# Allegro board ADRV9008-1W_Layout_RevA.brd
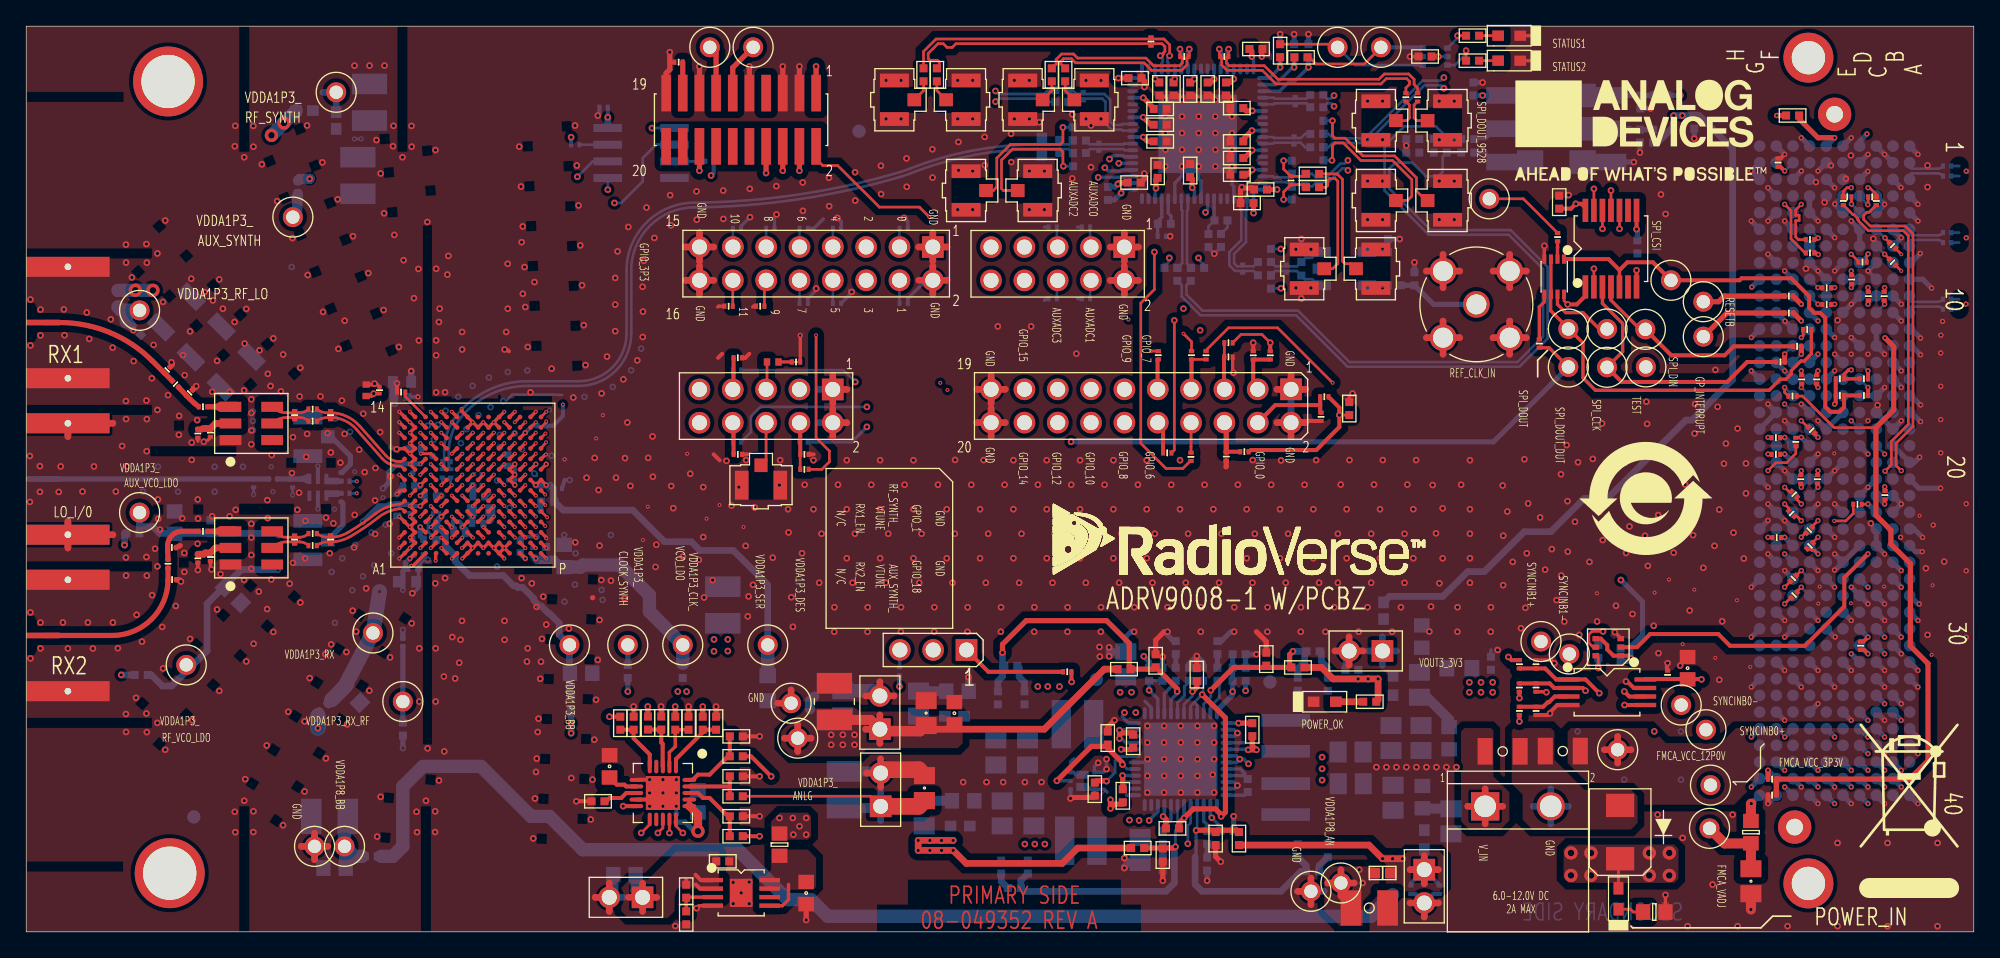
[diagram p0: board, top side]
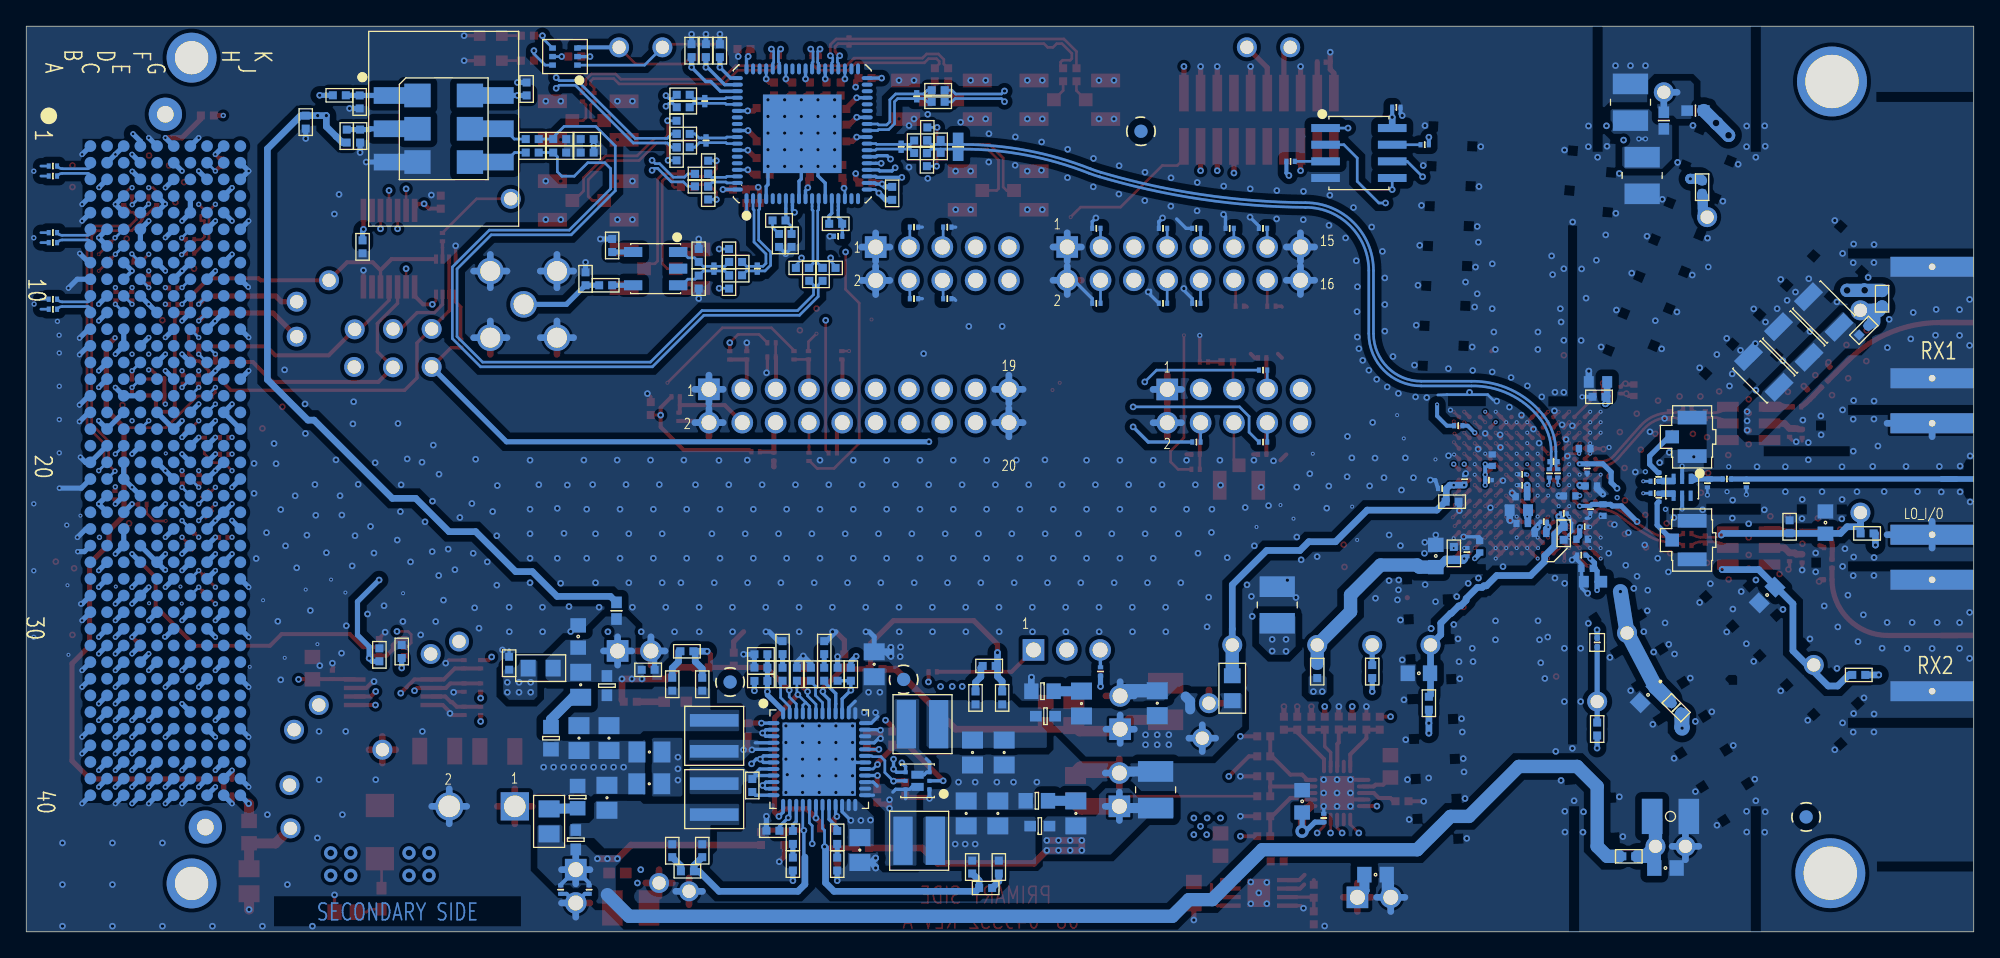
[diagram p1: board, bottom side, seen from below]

Outline 148.44 x 69.09 mm; copper layers: TOP, L2_GND, L3_PWR, L4_GND, L5_SIG, L6_GND, L7_SIG, L8_SIG, L9_GND, L10_SIG, L11_GND, L12_PWR, L13_GND, BOTTOM. Coordinates in mm from the lower left corner of the outline.
Outline path: 0,69.09 0,0 148.44,0 148.44,69.09 0,69.09

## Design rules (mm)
constraint set DEFAULT: min track width 0.203
net group DIFFPAIR0: nets SERDOUT0+ SERDOUT0-
net group DIFFPAIR1: nets SERDOUT1+ SERDOUT1-
net group DIFFPAIR2: nets SERDOUT3+ SERDOUT3-
net group DIFFPAIR13: nets SERDOUT2+ SERDOUT2-
net group DIFFPAIR26: nets GPIO_16 GPIO_17
net group DIFFPAIR27: nets GPIO_13 GPIO_14
net group DIFFPAIR28: nets GPIO_11 GPIO_12
net group DIFFPAIR29: nets GPIO_9 GPIO_10
net group DIFFPAIR30: nets GPIO_8 GPIO_15
net group DIFFPAIR37: nets SYNCINB0+ SYNCINB0-
net group DIFFPAIR38: nets SYNCINB1+ SYNCINB1-
net group DIFFPAIR56: nets SYSREF_IN+ SYSREF_IN-
net group DIFFPAIR59: nets CLK+ CLK-
net group DIFFPAIR63: nets FPGA_SYSREF+ FPGA_SYSREF-
net group DIFFPAIR72: nets VCXO_IN+ VCXO_IN-
net group DIFFPAIR74: nets FPGA_REF_CLK+ FPGA_REF_CLK-
net group DIFFPAIR75: nets DIR_CLK+ DIR_CLK-
net group DIFFPAIR76: nets UNNAMED_2_CAP_I91_N2 UNNAMED_2_CAP_I92_N2
net group DIFFPAIR77: nets UNNAMED_2_ADRV90081_I127_SERDOU UNNAMED_2_CAP_I94_N2
net group DIFFPAIR78: nets UNNAMED_2_CAP_I95_N2 UNNAMED_2_CAP_I98_N2
net group DIFFPAIR82: nets UNNAMED_2_CAP_I96_N2 UNNAMED_2_CAP_I97_N2
net group DIFFPAIR84: nets UNNAMED_7_CN400PAK_I55_N15 UNNAMED_7_CN400PAK_I55_N16
net group DIFFPAIR85: nets UNNAMED_7_CN400PAK_I55_N21 UNNAMED_7_CN400PAK_I55_N22
net group DIFFPAIR86: nets UNNAMED_7_CN400PAK_I52_N22 UNNAMED_7_CN400PAK_I52_N23
net group DIFFPAIR87: nets UNNAMED_7_CN400PAK_I55_N24 UNNAMED_7_CN400PAK_I55_N25
net group DIFFPAIR88: nets UNNAMED_4_CAP_I184_N1 UNNAMED_4_RES_I165_N2
net group DIFFPAIR89: nets OUT3 OUT3_N
net group DIFFPAIR91: nets OUT1 OUT1_N
net group DIFFPAIR92: nets UNNAMED_4_CAP_I166_N1 UNNAMED_4_CAP_I177_N1
net group DIFFPAIR93: nets OUT13 OUT13_N
net group DIFFPAIR94: nets OUT12 OUT12_N
net group DIFFPAIR96: nets UNNAMED_7_CAP_I157_N2 UNNAMED_7_CAP_I158_N2
net group DIFFPAIR98: nets SYSREF_CLK_IN+ SYSREF_CLK_IN-
net group DIFFPAIR99: nets FPGA_SYSREF_OUT+ FPGA_SYSREF_OUT-
net group DIFFPAIR100: nets UNNAMED_4_CNBNC3P_I324_CNTR UNNAMED_4_CNBNC3P_I325_CNTR
net group DIFFPAIR101: nets UNNAMED_4_CAP_I329_N1 UNNAMED_4_CAP_I330_N1
net group DIFFPAIR102: nets REF_CLK_IN+ REF_CLK_IN-
net group DIFFPAIR105: nets RX1_IN+ RX1_IN-
net group DIFFPAIR106: nets RX1_BAL+ RX1_BAL-
net group DIFFPAIR107: nets RF_EXT_LO+ RF_EXT_LO-
net group DIFFPAIR108: nets UNNAMED_10_CAP_I10_N1 UNNAMED_10_CAP_I11_N1
net group DIFFPAIR109: nets RX2_IN+ RX2_IN-
net group DIFFPAIR110: nets RX2_BAL+ RX2_BAL-
net group DIFFPAIR113: nets UNNAMED_4_CNBNC3P_I318_CNTR UNNAMED_4_CNBNC3P_I321_CNTR
net group DIFFPAIR114: nets UNNAMED_4_CAP_I292_N2 UNNAMED_4_CAP_I294_N2
net group DIFFPAIR115: nets OUT5 OUT5_N
net group DIFFPAIR116: nets UNNAMED_4_CAP_I303_N2 UNNAMED_4_CAP_I304_N2
net group DIFFPAIR117: nets OUT7 OUT7_N
net group DIFFPAIR118: nets UNNAMED_4_CNBNC3P_I306_CNTR UNNAMED_4_CNBNC3P_I308_CNTR
net group DIFFPAIR119: nets OUT8 OUT8_N
net group DIFFPAIR120: nets UNNAMED_4_CNBNC3P_I148_CNTR UNNAMED_4_CNBNC3P_I248_CNTR
nets with their own width: min track width 0.254; nets AGND

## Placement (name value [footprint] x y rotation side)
C6  0.1uF  [C0402]  111.64 20.49 270 bottom
C101  1uF  [C0402#2]  37.66 29.38 90 bottom
C102  1uF  [C0402#2]  30.8 33.25 0 bottom
C103  0.1uF  [C0201]  32.34 34.97 270 bottom
C104  0.1uF  [C0201]  31.71 34.97 270 bottom
C105  0.1uF  [C0201]  146.41 58.42 0 bottom
C106  0.1uF  [C0201]  146.41 57.66 0 bottom
C107  0.1uF  [C0201]  146.41 53.34 0 bottom
C108  0.1uF  [C0201]  146.41 52.58 0 bottom
C109  0.1uF  [C0201]  142.25 52.35 315 top
C110  0.1uF  [C0201]  142.25 51.08 315 top
C111  0.1uF  [C0201]  146.41 48.26 0 bottom
C112  0.1uF  [C0201]  146.41 47.5 0 bottom
C121  0.1uF  [C0201]  66.87 53.67 0 bottom
C122  0.1uF  [C0201]  66.87 47.95 0 bottom
C123  0.1uF  [C0201]  61.79 53.67 0 bottom
C124  0.1uF  [C0201]  61.79 47.95 0 bottom
C125  0.1uF  [C0201]  59.25 53.67 0 bottom
C126  0.1uF  [C0201]  59.25 47.95 0 bottom
C127  0.1uF  [C0201]  56.71 53.67 0 bottom
C128  0.1uF  [C0201]  55.95 47.73 180 top
C129  0.1uF  [C0201]  54.17 53.67 0 bottom
C130  0.1uF  [C0201]  53.53 47.73 180 top
C131  0.1uF  [C0201]  80.77 53.76 180 bottom
C132  0.1uF  [C0201]  80.77 48.3 180 bottom
C133  0.1uF  [C0201]  78.23 53.76 180 bottom
C134  0.1uF  [C0201]  78.23 48.3 180 bottom
C135  0.1uF  [C0201]  44.01 62.9 180 bottom
C136  1uF  [C0402#2]  56.9 43.47 0 top
C137  1uF  [C0402#2]  29.66 36.87 180 bottom
C201  TBD0201  [C0201]  10.74 42.87 45 top
C203  TBD0201  [C0201]  12.45 41.12 45 top
C204  TBD0201  [C0201]  20.46 39.42 90 top
C207  TBD0201  [C0201]  23.2 39.42 90 top
C208  TBD0201  [C0201]  11.12 26.87 0 top
C210  TBD0201  [C0201]  11.09 29.31 0 top
C211  TBD0201  [C0201]  20.46 29.92 90 top
C214  TBD0201  [C0201]  23.2 29.92 90 top
C240  10pF  [C0201]  13.08 38.01 90 top
C241  27PF  [C0201]  14.04 38.08 90 top
C242  82PF  [C0201]  14.04 28.59 90 top
C243  27PF  [C0201]  13.08 28.49 270 top
C248  18PF  [C0201]  13.47 40.05 0 top
C249  18PF  [C0201]  13.47 30.56 0 top
C301  TBD0201  [C0201]  17.33 34.23 270 bottom
C303  TBD0201  [C0201]  20.3 34.23 270 bottom
C304  100pF  [C0201]  24.32 34.37 0 bottom
C305  100pF  [C0201]  24.32 33.45 0 bottom
C401  0.1uF  [C0402]  104.28 49.32 180 bottom
C402  0.1uF  [C0402]  94.87 51.6 90 bottom
C403  0.1uF  [C0402]  94.37 51.1 180 bottom
C404  0.1uF  [C0402]  94.87 49.57 270 bottom
C405  0.1uF  [C0402]  94.37 50.09 180 bottom
C406  0.33uF  [C0402]  123.02 63.31 270 bottom
C407  0.1uF  [C0402]  110.3 64.3 270 bottom
C408  0.1uF  [C0402]  105.68 59.45 180 bottom
C409  0.1uF  [C0402]  88.76 50.16 90 bottom
C410  100pF  [C0201]  105.16 63.67 270 top
C411  100pF  [C0201]  106.05 63.67 270 top
C412  0.01uF  [C0402]  78.17 65.38 270 top
C413  0.01uF  [C0402]  79.19 65.38 270 top
C414  180pF  [C0402]  90.11 52.74 90 bottom
C415  1uF  [C0402]  91.06 52.74 90 bottom
C416  1000pF  [C0402]  86.74 54.01 0 bottom
C417  0.47uF  [C0201]  86.55 53.06 0 bottom
C418  0.1uF  [C0402]  86.43 60.3 0 top
C419  0.1uF  [C0402]  96.46 58.33 270 bottom
C420  0.1uF  [C0402]  96.46 56.36 90 bottom
C421  0.1uF  [C0402]  121.52 21.13 270 bottom
C422  0.1uF  [C0402]  119.82 21.38 270 bottom
C423  0.1uF  [C0402]  122.81 52.26 90 bottom
C424  0.1uF  [C0402]  116.84 55.67 270 top
C425  0.1uF  [C0402]  100.84 39.92 90 top
C426  1uF  [C0402]  86.24 58.02 90 top
C427  0.1uF  [C0402]  88.71 58.08 270 top
C428  0.1uF  [C0402]  93.04 55.6 0 top
C429  0.1uF  [C0402]  94.08 56.63 0 top
C430  0.1uF  [C0402]  92.27 57.76 0 top
C431  0.1uF  [C0402]  92.27 59.03 0 top
C432  0.1uF  [C0402]  92.27 60.3 0 top
C433  0.1uF  [C0402]  92.27 62.84 0 top
C434  0.1uF  [C0402]  93.73 67.35 180 top
C435  0.1uF  [C0402]  91.44 64.3 90 top
C436  0.1uF  [C0402]  90.05 64.3 90 top
C437  0.1uF  [C0402]  88.71 64.3 90 top
C438  0.1uF  [C0402]  87.44 64.3 90 top
C439  0.1uF  [C0402]  86.36 64.3 90 top
C440  0.1uF  [C0402]  106.62 66.78 0 top
C441  0.1uF  [C0402]  84.45 57.16 180 top
C442  0.1uF  [C0402]  86.43 61.57 180 top
C443  0.1uF  [C0402]  86.43 62.78 180 top
C444  0.1uF  [C0402]  84.51 65.13 180 top
C445  TBD0402  [C0402]  78.74 59.92 270 bottom
C601  10uF  [C0603]  70.74 16.68 90 top
C602  220UF  [C1210-2]  61.6 17.57 90 top
C603  10uF  [C0603]  42.29 19.72 0 bottom
C604  0.1uF  [C0201]  31.24 31.92 180 bottom
C605  1uF  [C0402]  31.25 30.4 270 bottom
C606  220UF  [C1210-2]  25.28 57.7 270 bottom
C607  220UF  [C1210-2]  26.16 63.29 90 bottom
C608  0.1uF  [C0201]  34.42 34.08 0 bottom
C609  1uF  [C0402#2]  34.48 33.19 0 bottom
C610  10uF  [C0603]  41 28.67 90 bottom
C611  0.1uF  [C0201]  38.63 28.96 90 bottom
C612  1uF  [C0402]  39.63 28.87 90 bottom
C613  10uF  [C0603#2]  29.02 26.71 0 bottom
C614  1uF  [C0402#2]  29.47 27.73 0 bottom
C615  0.1uF  [C0201]  29.91 28.74 0 bottom
C616  10uF  [C0603#2]  34.67 32.17 0 bottom
C617  1uF  [C0402#2]  34.42 31.15 0 bottom
C618  10uF  [C0603]  24.83 18.08 315 bottom
C619  0.1uF  [C0201]  29.66 30.9 180 bottom
C620  1uF  [C0402#2]  29.85 29.95 180 bottom
C621  10uF  [C0603]  11.31 31.22 90 bottom
C622  0.1uF  [C0201]  29.47 35.35 270 bottom
C623  1uF  [C0402]  14.04 30.9 90 bottom
C624  220UF  [C1210-2#2]  13.72 45 45 bottom
C625  220UF  [C1210-2#2]  11.43 47.28 45 bottom
C626  220UF  [C1210-2#2]  16 42.71 45 bottom
C627  1uF  [C0402#2]  29.15 34.01 180 bottom
C628  10uF  [C0603]  15.75 25.69 315 bottom
C629  0.1uF  [C0201]  29.21 32.23 270 bottom
C630  1uF  [C0402#2]  28.26 32.17 270 bottom
C631  10uF  [C0603#2]  28.64 41.95 0 bottom
C632  0.1uF  [C0201]  34.42 34.9 0 bottom
C633  1uF  [C0402]  28.56 40.81 0 bottom
C634  0.1uF  [C0201]  40.52 33.82 0 bottom
C635  1uF  [C0402]  39.76 32.81 180 bottom
C636  0.1uF  [C0201]  38.8 34.52 90 bottom
C640  220UF  [C1210-2]  62.36 10.83 90 bottom
C641  220UF  [C1210-2]  53.09 24.93 90 bottom
C642  0.1uF  [C0201]  36.96 34.46 180 bottom
C643  1uF  [C0402#2]  36.71 35.98 90 bottom
C701  0.1uF  [C0201]  49.54 8.68 270 bottom
C702  10uF  [C0603]  51.19 9.95 90 bottom
C703  10uF  [C0603]  126.63 20.11 90 top
C704  0.1uF  [C0201]  125.1 19.6 90 top
C705  10uF  [C0603]  44.46 12.62 90 top
C706  1uF  [C0402]  43.58 9.96 180 top
C801  0.01uF  [C0201]  140.7 56.06 180 top
C802  0.01uF  [C0201]  138.8 56.06 0 top
C803  0.01uF  [C0201]  141.01 55.76 270 top
C804  0.01uF  [C0201]  138.5 55.76 270 top
C901  10uF  [C0805H60]  83.81 20.41 90 bottom
C902  1uF  [C0402]  89.7 19.65 270 bottom
C903  1uF  [C0402]  89.22 19.62 270 top
C904  0.0027uF  [C0402]  87.62 21.68 270 bottom
C905  10uF  [C0805H60]  84.9 6.24 270 bottom
C906  0.0027uF  [C0402]  86.63 5.17 90 bottom
C907  10uF  [C0805H60]  100.94 13.72 0 bottom
C908  0.0033uF  [C0402]  90.79 21.68 270 bottom
C909  10uF  [C0805H60]  100.95 11.29 0 bottom
C910  0.0033uF  [C0402]  90 5.17 90 bottom
C911  TBD0402  [C0402]  86.6 19.65 270 bottom
C912  TBD0402  [C0402]  92.44 21.17 180 bottom
C913  0.1uF  [C0402]  84.37 14.54 90 top
C914  0.01uF  [C0402]  76.09 17.84 270 bottom
C915  0.1uF  [C0402]  83.58 10.38 90 top
C916  0.01uF  [C0402]  74.31 4.94 90 bottom
C917  0.1uF  [C0402]  93.45 15.42 270 top
C918  0.01uF  [C0402]  99.2 18.88 270 bottom
C919  0.1uF  [C0402]  93.1 11.16 90 bottom
C920  0.01uF  [C0402]  99.2 6.18 90 bottom
C921  47uF  [C0805H60]  76.31 13.68 270 bottom
C922  47uF  [C0805H60]  73.9 13.68 270 bottom
C924  47uF  [C0805H60]  68.01 17.41 90 bottom
C925  47uF  [C0805H60]  76.8 9.03 90 bottom
C926  47uF  [C0805H60]  74.38 9.03 90 bottom
C927  47uF  [C0805H60]  68.44 9.03 90 bottom
C928  47uF  [C0805H60]  104.02 14.78 270 bottom
C929  47uF  [C0805H60]  106.18 18.84 270 bottom
C930  47uF  [C0805H60]  104.18 10.22 90 bottom
C931  22uF  [C0805H53]  108.59 8.42 90 bottom
C932  47uF  [C0805H60]  131.45 3.86 270 top
C933  4.7uF  [C0603]  59.45 2.96 90 top
C934  4.7uF  [C0603]  45.6 4.36 0 bottom
C935  0.01uF  [C0402]  53.09 5.37 180 top
C936  10uF  [C0603]  106.37 22.53 90 bottom
C937  0.01uF  [C0402]  101.04 19.99 0 bottom
C938  0.1uF  [C0402]  127.14 61.77 90 bottom
C939  47uF  [C0805H60]  106.31 14.78 270 bottom
C940  0.1uF  [C0201]  105.54 3.21 90 bottom
C941  0.01uF  [C0201]  107.7 3.21 90 bottom
C942  100uF  [C1210]  23.12 8.8 180 bottom
C943  10uF  [C0603]  23.5 4.87 180 bottom
C944  0.1uF  [C0201]  32.77 31.28 0 bottom
C945  1uF  [C0402#2]  33.02 30.39 0 bottom
C946  100uF  [C1210]  102.36 1.82 0 top
C947  0.1uF  [C0201]  26.93 41.31 90 top
C948  1uF  [C0402#2]  25.91 41.31 90 top
C949  47uF  [C0805H60]  62.23 17.44 90 bottom
C950  47uF  [C0805H60]  68.59 16.68 90 top
C951  47uF  [C0805H60]  68.46 10.97 90 top
CR901  S2A-LT  [DO214AA3]  121.48 7.6 90 top
DS401  LNJ326W83RA  [LED0603_A]  113.03 66.46 180 top
DS402  LNJ326W83RA  [LED0603_A]  113.03 68.37 180 top
DS901  LNJ926W8CRA  [LED0603]  121.36 2.52 90 top
DS902  LNJ326W83RA  [LED0603_A]  98.97 17.55 0 top
E602  1.8K OHM AT 100MEGHZ  [L0402]  21.21 62.65 0 bottom
E611  42OHM AT 100MEGHZ  [L0805]  56.52 18.58 90 bottom
E613  1.8KOHM AT 100MEGHZ  [L0402]  23.62 61.89 270 bottom
E901  120OHM  [L0603]  70.75 16.45 180 bottom
E902  470OHM  [L0603]  71.18 8.06 180 bottom
E903  470OHM  [L0603]  104.18 18.78 90 bottom
E904  470OHM  [L0603]  106.56 7.02 270 bottom
E905  42OHM AT 100MEGHZ  [L0805]  109.23 20.11 0 bottom
E906  30OHM  [L0402]  103.45 24.49 90 bottom
E907  30OHM  [L0402]  103.38 4.48 180 top
F901  2A  [F1206]  117.11 13.78 180 top
F902  2A  [F1206]  112.53 13.76 0 top
J101  U.FL-R-SMT-1(01)  [CNHIROSE-U_FL-R-SMT-1]  56 34.07 180 top
J201  132255-11  [CNAMPHENOL132255-11]  0.76 46.48 180 top
J202  132255-11  [CNAMPHENOL132255-11]  0.76 22.61 180 top
J301  132255-11  [CNAMPHENOL132255-11]  0.76 34.54 180 bottom
J305  U.FL-R-SMT-1(01)  [CNHIROSE-U_FL-R-SMT-1]  21.47 37.76 270 bottom
J306  U.FL-R-SMT-1(01)  [CNHIROSE-U_FL-R-SMT-1]  21.47 29.88 270 bottom
J401  142-0701-201  [CNJOHNSON142-0701-201]  110.53 47.87 0 top
J402  U.FL-R-SMT-1(01)  [CNHIROSE-U_FL-R-SMT-1]  102.87 55.79 90 top
J403  U.FL-R-SMT-1(01)  [CNHIROSE-U_FL-R-SMT-1]  108.33 55.79 270 top
J404  U.FL-R-SMT-1(01)  [CNHIROSE-U_FL-R-SMT-1]  102.87 61.89 90 top
J405  U.FL-R-SMT-1(01)  [CNHIROSE-U_FL-R-SMT-1]  108.33 61.89 270 top
J406  U.FL-R-SMT-1(01)  [CNHIROSE-U_FL-R-SMT-1]  75.95 63.48 90 top
J407  U.FL-R-SMT-1(01)  [CNHIROSE-U_FL-R-SMT-1]  81.41 63.48 270 top
J408  U.FL-R-SMT-1(01)  [CNHIROSE-U_FL-R-SMT-1]  71.63 63.48 270 top
J409  U.FL-R-SMT-1(01)  [CNHIROSE-U_FL-R-SMT-1]  66.17 63.48 90 top
J410  U.FL-R-SMT-1(01)  [CNHIROSE-U_FL-R-SMT-1]  71.63 56.55 90 top
J411  U.FL-R-SMT-1(01)  [CNHIROSE-U_FL-R-SMT-1]  77.09 56.55 270 top
J412  U.FL-R-SMT-1(01)  [CNHIROSE-U_FL-R-SMT-1]  102.87 50.59 270 top
J413  U.FL-R-SMT-1(01)  [CNHIROSE-U_FL-R-SMT-1]  97.41 50.59 90 top
L401  TBD0402  [L0402]  77.41 59.89 90 bottom
L612  TBD0201  [L0201]  28.7 22.07 90 bottom
L900  2.2uH  [LSMSQ157H83]  80.12 15.84 180 bottom
L901  2.2uH  [LSMSQ157H83]  80.38 6.95 180 bottom
L902  6.8uH  [LSMSQ157H122]  96 14.95 90 bottom
L903  6.8uH  [LSMSQ157H122]  96 10.12 270 bottom
NOREF  -  []  65.26 90.52 0 top
NOREF#2  -  [unnamed#2]  10.81 64.87 0 top
NOREF#3  -  []  -140.27 -283.34 0 top
NOREF#4  -  []  152.78 19.47 0 top
NOREF#5  -  []  123.45 33.06 0 top
NOREF#6  -  []  250.38 218.8 0 top
NOREF#7  -  []  0 69.09 0 top
NOREF#8  -  [unnamed#2]  135.84 66.69 0 top
NOREF#9  -  []  123.07 61.13 0 top
NOREF#10  -  []  100.91 114.35 0 top
NOREF#11  -  []  3.55 -12.7 90 top
NOREF#12  -  [unnamed#2]  10.93 4.47 0 top
NOREF#13  -  []  154.73 137.11 0 top
NOREF#14  -  []  148.44 0 90 top
NOREF#15  -  []  280.93 -40.72 0 top
NOREF#16  -  []  -140.27 -283.34 0 top
NOREF#17  -  [unnamed#2]  135.84 3.69 0 top
NOREF#18  -  []  -140.27 -283.34 0 top
NOREF#19  -  []  -96.05 -19.57 0 top
NOREF#20  -  [unnamed#2]  94.79 19.06 0 bottom
NOREF#21  -  [unnamed#2]  12.78 8.76 0 bottom
NOREF#22  -  [unnamed#2]  81.56 19.25 0 bottom
NOREF#23  -  [unnamed#2]  63.47 61.07 90 bottom
P101  TSW-110-08-G-D  [CNBERG2X10H330LD36]  96.4 41.39 180 top
P102  TSW-108-08-G-D  [CNSAMTECTSW-108-08-G-D-ST]  69.1 52.24 180 top
P103  TSW-105-08-G-D  [CNSAMTEC2X5H338LD36]  83.7 52.24 180 top
P104  TSW-105-08-G-D  [CNSAMTEC2X5H338LD36]  61.47 41.38 180 top
P701  FTSH-110-01-L-DV-K  [CNHDR2X10H251]  54.49 61.95 180 top
P801  ASP-134488-01  [CNSAMTECASP-134488-01]  143.55 59.94 270 bottom
P901  Z5.530.3225.0  [CNWIELAND3225]  111.2 9.57 0 top
P902  TSW-103-08-G-S  [CNBERG1X3H205LD36]  71.67 21.5 180 top
P903  TSW-102-08-G-S  [CNSAMTEC1X2H330LD36]  65.06 16.73 90 top
P904  TSW-102-08-G-S  [CNSAMTEC1X2H330LD36]  65.12 10.84 90 top
P905  TSW-102-08-G-S  [CNSAMTEC1X2H330LD36]  102.1 21.42 180 top
P906  TSW-102-08-G-S  [CNSAMTEC1X2H330LD36]  106.56 3.47 270 top
P907  TSW-102-08-G-S  [CNSAMTEC1X2H330LD36]  45.71 2.63 180 top
Q901  SIA906EDJ-T1-GE3  [POWERPAKSC70-6]  80.51 11.52 90 bottom
R101  14.3K  [R0201]  28.57 41.18 180 top
R102  10K  [R0201]  91.63 44.93 180 top
R103  10K  [R0201]  91.63 43.85 0 top
R104  10K  [R0201]  92.85 36.62 180 top
R105  10K  [R0201]  91.46 36.25 270 top
R106  10K  [R0201]  94.81 43.98 270 top
R107  10K  [R0201]  93.52 43.98 90 top
R108  10K  [R0201]  98.94 40.81 180 top
R109  10K  [R0201]  98.69 39.29 270 top
R110  10K  [R0201]  39.29 38.61 0 bottom
R111  10K  [R0201]  133.07 11.65 0 top
R112  1K  [R0201]  133.07 10.43 180 top
R113  10K  [R0201]  59.31 36.43 0 top
R116  10K  [R0201]  54.23 36.43 0 top
R117  10K  [R0201]  54.23 43.79 0 top
R118  10K  [R0201]  58.68 43.47 0 top
R119  10K  [R0201]  41.85 60.05 0 bottom
R120  10K  [R0201]  52.07 58.78 180 bottom
R121  100  [R0201]  32.03 35.86 180 bottom
R202  0  [R0201]  11.38 41.78 315 top
R205  0  [R0201]  21.83 38.96 0 top
R206  0  [R0201]  21.83 39.87 0 top
R209  0  [R0201]  10.8 28.08 90 top
R212  0  [R0201]  21.83 29.47 0 top
R213  0  [R0201]  21.83 30.38 0 top
R302  0  [R0201]  18.82 34.54 0 bottom
R304  0  [R0201]  24.01 34.71 270 bottom
R305  0  [R0201]  24.01 33.12 90 bottom
R401  49.9  [R0402]  105.81 49.82 270 bottom
R402  0  [R0402]  103.78 52.36 270 bottom
R403  24.9  [R0402]  97.18 51.6 90 bottom
R404  24.9  [R0402]  97.18 49.57 90 bottom
R405  100  [R0201]  96.02 50.59 270 bottom
R406  100  [R0201]  92.72 50.59 270 bottom
R407  0  [R0402]  124.57 63.82 180 bottom
R408  0  [R0402]  124.01 60.71 90 bottom
R409  0  [R0402]  122.99 60.71 90 bottom
R410  0  [R0402]  109.87 59.45 180 bottom
R411  0  [R0402]  87.74 50.16 90 bottom
R412  49.9  [R0402]  107.78 59.45 0 bottom
R413  0  [R0402]  107.78 60.48 180 bottom
R414  0  [R0402]  105.68 60.48 180 bottom
R415  0  [R0402]  87.25 50.65 180 bottom
R416  0  [R0402]  89.28 50.65 0 bottom
R417  0  [R0402]  109.87 60.48 180 bottom
R418  100  [R0201]  96.63 60.37 270 bottom
R419  0  [R0402]  98.36 59.86 0 bottom
R420  0  [R0402]  98.36 60.87 0 bottom
R421  0  [R0402]  98.87 59.35 90 bottom
R422  0  [R0402]  98.87 61.38 270 bottom
R423  100  [R0201]  96.72 63.38 90 bottom
R424  0  [R0402]  98.36 63.86 0 bottom
R425  0  [R0402]  98.36 62.9 0 bottom
R426  100  [R0201]  91.32 66.78 0 top
R427  100  [R0201]  88.27 66.78 0 top
R428  100  [R0201]  85.73 67.92 90 top
R429  0  [R0402]  69.41 65.38 270 top
R430  0  [R0402]  68.39 65.38 270 top
R431  100  [R0201]  80.57 63.74 270 bottom
R432  0  [R0402]  78.93 63.32 180 bottom
R433  0  [R0402]  78.93 64.21 180 bottom
R434  100  [R0201]  81.75 59.89 90 bottom
R435  0  [R0402]  80.27 60.36 180 bottom
R436  0  [R0402]  80.27 59.41 180 bottom
R437  0  [R0402]  79.76 60.87 90 bottom
R438  0  [R0402]  79.79 58.9 270 bottom
R439  10.2K  [R0402]  91.06 54.27 180 bottom
R440  10K  [R0402]  82.44 56.34 270 bottom
R441  10K  [R0402]  97.73 67.22 270 bottom
R442  10K  [R0402]  95.57 67.22 90 bottom
R443  10K  [R0402]  96.64 67.22 90 bottom
R444  0  [R0402]  95.57 67.22 90 top
R445  0  [R0402]  97.16 66.71 0 top
R446  200  [R0402]  110.24 66.46 0 top
R447  200  [R0402]  110.24 68.37 0 top
R448  0  [R0402]  98.05 57.82 180 top
R449  0  [R0402]  98.05 56.81 180 top
R450  100  [R0201]  96.4 57.32 270 top
R451  0  [R0402]  96.97 57.82 180 bottom
R452  0  [R0402]  96.97 56.87 180 bottom
R453  0  [R0201]  116.72 53 90 top
R454  0  [R0201]  115.33 44.88 270 top
R601  0  [R0402]  41.53 17.44 90 bottom
R603  0  [R0402]  50.04 19.85 90 bottom
R604  0  [R0402]  28.7 15.47 90 bottom
R605  0  [R0402]  45.85 19.85 90 bottom
R606  0  [R0402]  22.68 17.1 45 bottom
R607  0  [R0402]  8.13 30.39 0 bottom
R608  0  [R0402]  6.99 48.3 270 bottom
R609  0  [R0402]  8.77 19.6 0 bottom
R610  0  [R0402]  20.7 56.81 270 bottom
R612  0  [R0201]  28.7 22.07 90 bottom
R613  0.1  [R0402]  8.38 45.89 315 bottom
R701  47K  [R0201]  49.72 66.35 0 top
R702  0  [R0201]  86.28 43.99 270 top
R704  0  [R0201]  59.31 35.28 180 top
R705  0  [R0201]  88.82 43.99 270 top
R706  0  [R0201]  86.97 36.53 180 top
R707  0  [R0201]  88.78 36.23 90 top
R708  20K  [R0201]  113.8 20.41 90 top
R709  20K  [R0201]  113.8 18.63 270 top
R710  20K  [R0201]  113.8 16.85 270 top
R711  20K  [R0201]  115.07 20.41 270 top
R712  20K  [R0201]  115.07 18.63 90 top
R713  20K  [R0201]  115.07 16.85 90 top
R714  56K  [R0402]  54.12 7.29 0 top
R715  10K  [R0402]  54.12 8.81 0 top
R716  10K  [R0402]  54.12 10.34 180 top
R717  10K  [R0402]  54.12 11.86 180 top
R718  10K  [R0402]  54.12 13.39 180 top
R719  10K  [R0402]  54.12 14.91 180 top
R720  10K  [R0402]  51.56 15.91 270 top
R721  10K  [R0402]  52.58 15.91 270 top
R722  10K  [R0402]  49.47 15.91 270 top
R723  10K  [R0402]  50.48 15.91 270 top
R724  10K  [R0402]  47.39 15.93 270 top
R725  10K  [R0402]  48.4 15.93 270 top
R726  10K  [R0402]  45.28 15.91 270 top
R727  10K  [R0402]  46.29 15.91 270 top
R801  0  [R0201]  133.52 58.69 270 top
R804  0  [R0201]  134.34 48.5 0 top
R805  0  [R0201]  134.34 47.21 0 top
R806  0  [R0201]  133.71 43.47 0 top
R807  0  [R0201]  134.98 44.67 0 top
R808  0  [R0201]  133.35 37.7 0 top
R809  0  [R0201]  133.35 36.43 0 top
R810  0  [R0201]  134.75 33.38 315 top
R811  0  [R0201]  134.56 31.92 315 top
R812  0  [R0201]  133.42 30.08 0 top
R813  0  [R0201]  89.92 43.98 90 top
R816  0  [R0201]  140.4 48.49 270 top
R817  0  [R0201]  141.61 48.49 270 top
R818  0  [R0201]  135.96 52.81 0 top
R819  0  [R0201]  135.96 51.79 0 top
R820  0  [R0201]  137.23 49.13 180 top
R821  0  [R0201]  137.23 47.86 180 top
R822  0  [R0201]  136.08 38.27 315 top
R823  0  [R0201]  134.88 37.38 90 top
R824  0  [R0201]  135.26 34.52 270 top
R825  0  [R0201]  136.53 34.52 270 top
R826  0  [R0201]  135.89 30.65 45 top
R827  0  [R0201]  135.96 29.44 225 top
R828  0  [R0201]  134.69 26.96 45 top
R829  0  [R0201]  134.75 25.69 45 top
R830  0  [R0201]  136.46 42.14 270 top
R831  0  [R0201]  135.32 42.14 270 top
R832  10K  [R0201]  138.24 42.19 0 top
R833  10K  [R0201]  138.24 40.92 0 top
R834  0  [R0201]  139.96 51.09 0 top
R835  0  [R0201]  139.13 49.76 270 top
R836  0  [R0201]  134.62 40.87 180 top
R837  0  [R0201]  59.25 37.37 0 bottom
R839  0  [R0201]  54.17 42.85 0 bottom
R840  0  [R0201]  139.81 21.83 90 top
R842  0  [R0201]  54.17 37.37 0 bottom
R843  0  [R0201]  141.67 33.31 270 top
R844  0  [R0201]  139.58 32.62 0 top
R845  0  [R0201]  135.75 45.94 180 top
R846  0  [R0201]  140.06 42.19 0 top
R847  0  [R0201]  140.06 40.92 0 top
R848  1K  [R0402]  134.63 62.28 0 top
R901  2K  [R0603]  124.09 1.51 180 top
R902  200  [R0201]  79.35 19.83 180 top
R903  100K  [R0402]  87.36 7.89 0 top
R904  10K  [R0402]  87.62 19.65 270 bottom
R905  43.2K  [R0402]  85.59 19.65 270 bottom
R906  100K  [R0402]  91.53 7.71 0 bottom
R907  10K  [R0402]  86.63 7.2 90 bottom
R908  20K  [R0402]  90.79 19.65 270 bottom
R909  56K  [R0402]  92.44 19.14 180 bottom
R910  14K  [R0402]  92.44 20.15 0 bottom
R911  20K  [R0402]  90 7.2 90 bottom
R912  0  [R0201]  66.56 19.86 270 bottom
R913  22.1K  [R0402]  88.63 19.65 90 bottom
R914  10K  [R0402]  86.08 20.67 90 top
R915  0  [R0402]  75.04 20.28 0 bottom
R916  6.34K  [R0402]  83.67 20.04 180 top
R917  10.7K  [R0402]  74.05 17.84 270 bottom
R918  47K  [R0402]  81.45 10.88 90 top
R919  47K  [R0402]  82.43 14.78 270 top
R920  10K  [R0402]  86.63 5.85 90 top
R921  0  [R0402]  75.31 3.34 180 bottom
R922  10K  [R0402]  76.34 4.94 90 bottom
R923  6.34K  [R0402]  84.71 6.39 180 top
R924  10K  [R0402]  94.51 20.8 270 top
R925  0  [R0402]  98.08 21.4 0 bottom
R926  37.4K  [R0402]  96.91 18.88 270 bottom
R927  31.6K  [R0402]  96.93 20.17 0 top
R928  10K  [R0402]  90.65 7.11 90 top
R929  0  [R0402]  98.05 4.61 0 bottom
R930  27.4K  [R0402]  96.91 6.18 90 bottom
R931  12.7K  [R0402]  92.43 7.11 270 top
R932  0.1  [R0603]  70.98 18.35 0 bottom
R933  0.1  [R0603]  71.41 9.99 0 bottom
R934  0.1  [R0603]  108.45 14.77 270 bottom
R935  200  [R0402]  102.4 17.55 180 top
R936  0  [R0603]  57.41 6.65 270 top
R937  0.47  [R0603]  106.41 10.27 90 bottom
R938  0  [R0603]  131.45 7.6 90 top
R939  20K  [R0402]  50.3 3.09 90 top
R940  4.99K  [R0402]  50.3 1.06 90 top
R941  0  [R0402]  103.38 4.48 180 top
R942  0  [R0402]  26.29 5.75 180 bottom
T201  TCM1-83X+  [TSML150W160H160]  17.15 38.78 90 top
T202  TCM1-83X+  [TSML150W160H160]  17.15 29.29 90 top
T301  HHM1595A1  [T0805_A]  22.23 33.91 0 bottom
T401  MABA-007159-000000  [ETC1]  100.47 50.59 270 bottom
TP400  WHT  [CNKEY5001TP]  111.51 55.92 0 top
TP401  WHT  [CNKEY5001TP]  117.54 43.09 0 top
TP402  WHT  [CNKEY5001TP]  103.25 67.48 180 top
TP403  WHT  [CNKEY5001TP]  99.95 67.48 180 top
TP601  WHT  [CNKEY5001TP]  58.8 14.77 0 top
TP602  WHT  [CNKEY5001TP]  58.3 17.44 0 top
TP603  WHT  [CNKEY5001TP]  41.4 21.88 0 top
TP604  WHT  [CNKEY5001TP]  23.62 64.05 0 top
TP605  WHT  [CNKEY5001TP]  50.04 21.88 0 top
TP606  WHT  [CNKEY5001TP]  28.7 17.57 0 top
TP607  WHT  [CNKEY5001TP]  45.85 21.88 0 top
TP608  WHT  [CNKEY5001TP]  26.42 22.8 0 top
TP609  WHT  [CNKEY5001TP]  8.64 31.98 0 top
TP610  WHT  [CNKEY5001TP]  8.64 47.41 0 top
TP611  WHT  [CNKEY5001TP]  12.19 20.36 0 top
TP612  WHT  [CNKEY5001TP]  20.32 54.52 0 top
TP613  WHT  [CNKEY5001TP]  56.52 21.88 0 top
TP701  WHT  [CNKEY5001TP]  52.1 67.48 180 top
TP702  WHT  [CNKEY5001TP]  55.4 67.48 180 top
TP803  WHT  [CNKEY5001TP]  127.83 48.07 0 top
TP804  WHT  [CNKEY5001TP]  127.83 45.4 0 top
TP805  WHT  [CNKEY5001TP]  120.48 43.07 0 top
TP806  WHT  [CNKEY5001TP]  123.41 45.96 0 top
TP809  WHT  [CNKEY5001TP]  128.03 15.41 45 top
TP810  WHT  [CNKEY5001TP]  126.14 17.3 45 top
TP811  WHT  [CNKEY5001TP]  117.54 45.99 0 top
TP812  WHT  [CNKEY5001TP]  115.45 22.14 0 top
TP813  WHT  [CNKEY5001TP]  117.61 21.19 0 top
TP814  WHT  [CNKEY5001TP]  128.3 7.89 0 top
TP815  WHT  [CNKEY5001TP]  125.36 49.7 0 top
TP816  WHT  [CNKEY5001TP]  120.48 45.99 0 top
TP817  WHT  [CNKEY5001TP]  123.45 43.09 0 top
TP818  WHT  [CNKEY5001TP]  128.37 11.19 0 top
TP819  WHT  [CNKEY5001TP]  121.29 13.89 0 top
TP901  WHT  [CNKEY5001TP]  100.21 3.72 0 top
TP902  WHT  [CNKEY5001TP]  97.92 3.09 0 top
TP903  WHT  [CNKEY5001TP]  24.26 6.52 0 top
TP904  WHT  [CNKEY5001TP]  21.97 6.52 0 top
U101  ADRV9008BBCZ-1  [BGA196]  34.04 34.08 0 top
U102  S25FL208K0RMFI041  [SO8]  46.87 59.41 270 bottom
U401  AD9528BCPZ  [QFN72_10X10_PAD5_3X5_3]  89.29 60.88 180 bottom
U402  NC7WV125K8X  [US8]  116.46 49.98 180 top
U403  ADG3304SRU-EP  [TSSOP14]  120.79 52.12 0 top
U404  ADG3301BKSZ  [SC70-6]  120.58 21.71 90 top
U405  NC7WZ16P6X  [SC70]  107.37 66.77 90 bottom
U702  M24C02-FDW6TP  [TSSOP8]  120.48 18.28 270 top
U703  AD7291BCPZ  [QFN20_4X4_PAD2_6X2_6]  48.52 10.59 180 top
U901  ADP5054ACPZ  [QFN48_7X7_PAD5_6X5_6]  88 13.17 270 bottom
U902  ADP125ARHZ-R7  [MSOP8_PAD2_16X1_73]  54.49 2.97 270 top
Y401  122.88MEGHZ  [YSML276W197H71]  116.62 61.26 270 bottom
Y402  122.88MEGHz  [YSML555W358H240]  116.62 61.26 270 bottom

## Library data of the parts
C6 C401-C405 C407-C409 C418-C425 C427-C444 C913 C915 C917 C919 C938 = CAP: User Part Number: UPN; Tolerance: 10; alternate symbols: (); part number: CAP_SM-0.1UF,16V,10,E007200,C0402; tolerance: 10
C101 C102 C136 C137 C609 C614 C617 C620 C627 C630 C643 C945 C948 = CAP: Tolerance: 10; User Part Number: UPN; alternate symbols: (C0402L_ALT); part number: CAP_SM-1UF,6.3V,10,E007449,C0402; tolerance: 10
C103-C112 C121-C135 C701 C704 C940 = CAP: Tolerance: 10; User Part Number: UPN; alternate symbols: (); part number: CAP_SM-0.1UF,6.3V,10,E011567,C0201; tolerance: 10
C201 C203 C204 C207 C208 C210 C211 C214 C301 C303 = CAP: User Part Number: UPN; alternate symbols: (); part number: CAP_SM-TBD0201,TBD0201,TBD0201,E005718,C0201
C240 = CAP: Tolerance: 5; User Part Number: UPN; alternate symbols: (); part number: CAP_SM-10PF,25V,5,E022849,C0201; tolerance: 5
C241 C243 = CAP: Tolerance: 5; User Part Number: UPN; alternate symbols: (); part number: CAP_SM-27PF,25V,5,E031190,C0201; tolerance: 5
C242 = CAP: Tolerance: 5; User Part Number: UPN; alternate symbols: (); part number: CAP_SM-82PF,25V,5,E025826,C0201; tolerance: 5
C248 C249 = CAP: Tolerance: 5; User Part Number: UPN; alternate symbols: (); part number: CAP_SM-18PF,50V,5,E028398,C0201; tolerance: 5
C304 C305 C410 C411 = CAP: Tolerance: 10; User Part Number: UPN; alternate symbols: (); part number: CAP_SM-100PF,25V,10,E006763,C0201; tolerance: 10
C406 = CAP: User Part Number: UPN; Tolerance: 10; alternate symbols: (); part number: CAP_SM-0.33UF,10V,10,E011273,C0402; tolerance: 10
C412 C413 C914 C916 C918 C920 C935 C937 = CAP: User Part Number: UPN; Tolerance: 10; alternate symbols: (); part number: CAP_SM-0.01UF,25V,10,E010983,C0402; tolerance: 10
C414 = CAP: User Part Number: UPN; Tolerance: 5; alternate symbols: (); part number: CAP_SM-180PF,50V,5,E012612,C0402; tolerance: 5
C415 C426 C706 C902 C903 = CAP: User Part Number: UPN; Tolerance: 10; alternate symbols: (); part number: CAP_SM-1UF,6.3V,10,E007449,C0402; tolerance: 10
C416 = CAP: User Part Number: UPN; Tolerance: 5; alternate symbols: (C0402L_ALT); part number: CAP_SM-1000PF,50V,5,E012419,C0402; tolerance: 5
C417 = CAP: Tolerance: 20; User Part Number: UPN; alternate symbols: (); part number: CAP_SM-0.47UF,4V,20,E008196,C0201; tolerance: 20
C445 = CAP: User Part Number: UPN; alternate symbols: (C0402L_ALT); part number: CAP_SM-TBD0402,TBD0402,TBD0402,E000381,C0402
C601 C702 C703 C705 C936 C943 = CAP: Tolerance: 20; User Part Number: UPN; alternate symbols: (); part number: CAP_SM-10UF,6.3V,20,E007143,C0603; tolerance: 20
C602 C606 C607 C640 C641 = CAP: Tolerance: 20; User Part Number: UPN; alternate symbols: (); part number: CAP_SM-220UF,6.3V,20,E031200,C1210-2; tolerance: 20
C603 C610 C618 C621 C628 = CAP: Tolerance: 20; User Part Number: UPN; alternate symbols: (C0603L); part number: CAP_SM-10UF,6.3V,20,E007143,C0603; tolerance: 20
C604 C608 C611 C615 C619 C622 C629 C632 C634 C636 C642 C944 C947 = CAP: Tolerance: 10; User Part Number: UPN; alternate symbols: (C0201-2); part number: CAP_SM-0.1UF,6.3V,10,E011567,C0201; tolerance: 10
C605 C612 C623 C633 C635 = CAP: User Part Number: UPN; Tolerance: 10; alternate symbols: (C0402L_ALT); part number: CAP_SM-1UF,6.3V,10,E007449,C0402; tolerance: 10
C613 C616 C631 = CAP: User Part Number: UPN; Tolerance: 20; alternate symbols: (C0603L); part number: CAP_SM-10UF,6.3V,20,E007143,C0603; tolerance: 20
C624-C626 = CAP: User Part Number: UPN; Tolerance: 20; alternate symbols: C1210H106; part number: CAP_SM-220UF,6.3V,20,E031200,C1210-2; tolerance: 20
C801-C804 C941 = CAP: Tolerance: 10; User Part Number: UPN; alternate symbols: (); part number: CAP_SM-0.01UF,10V,10,E007201,C0201; tolerance: 10
C901 C905 C907 C909 = CAP: Tolerance: 10; User Part Number: UPN; alternate symbols: (); part number: CAP_SM-10UF,25V,10,E014704,C0805H60; tolerance: 10
C904 C906 = CAP: User Part Number: UPN; Tolerance: 10; alternate symbols: (); part number: CAP_SM-0.0027UF,50V,10,E006649,C0402; tolerance: 10
C908 C910 = CAP: User Part Number: UPN; Tolerance: 10; alternate symbols: (); part number: CAP_SM-0.0033UF,50V,10,E007461,C0402; tolerance: 10
C911 C912 = CAP: User Part Number: UPN; alternate symbols: (); part number: CAP_SM-TBD0402,TBD0402,TBD0402,E000381,C0402
C921 C922 C924-C930 C932 C939 C949-C951 = CAP: Tolerance: 20; User Part Number: UPN; alternate symbols: (C0805L); part number: CAP_SM-47UF,6.3V,20,E008247,C0805H60; tolerance: 20
C931 = CAP: Tolerance: 20; User Part Number: UPN; alternate symbols: (); part number: CAP_SM-22UF,6.3V,20,E006534,C0805H53; tolerance: 20
C933 C934 = CAP: Tolerance: 10; User Part Number: UPN; alternate symbols: (); part number: CAP_SM-4.7UF,6.3V,10,E010382,C0603; tolerance: 10
C942 C946 = CAP: Tolerance: 20; User Part Number: UPN; alternate symbols: (); part number: CAP_SM-100UF,6.3V,20,E006532,C1210; tolerance: 20
CR901 = DIO: User Part Number: UPN; Tolerance: N/A; alternate symbols: (); part number: DIO_SM-S2A-LT,50V,N/A,E006935,DO214AA3; tolerance: N/A
DS401 DS402 DS902 = DIOLED: User Part Number: UPN; Tolerance: N/A; alternate symbols: (); part number: DIOLED_SM-LNJ326W83RA,2.5V,N/A,E027189,LED0603_A; tolerance: N/A
DS901 = DIOLED: Tolerance: N/A; User Part Number: UPN; alternate symbols: (); part number: DIOLED_SM-LNJ926W8CRA,N/A,N/A,E008232,LED0603; tolerance: N/A
E602 = FERRITE: Tolerance: 25; User Part Number: UPN; alternate symbols: (); part number: FERRITE_SM-1.8K OHM AT 100MEGHZ,25,E025769,L0402; tolerance: 25
E611 E905 = FERRITE: Tolerance: 25; User Part Number: UPN; alternate symbols: (); part number: FERRITE_SM-42OHM AT 100MEGHZ,25,E022207,L0805; tolerance: 25
E613 = FERRITE: Tolerance: 25; User Part Number: UPN; alternate symbols: (); part number: FERRITE_SM-1.8KOHM AT 100MEGHZ,25,E026780,L0402; tolerance: 25
E901 = FERRITE: Tolerance: 25; User Part Number: UPN; alternate symbols: (); part number: FERRITE_SM-120OHM,25,E012242,L0603; tolerance: 25
E902-E904 = FERRITE: Tolerance: 25; User Part Number: UPN; alternate symbols: (); part number: FERRITE_SM-470OHM,25,E021228,L0603; tolerance: 25
E906 E907 = FERRITE: Tolerance: 25; User Part Number: UPN; alternate symbols: (); part number: FERRITE_SM-30OHM,25,E015998,L0402; tolerance: 25
F901 F902 = FSFUSE: Tolerance: N/A; User Part Number: UPN; alternate symbols: (); part number: FSFUSE_SM-2A,63V,E005321,F1206; tolerance: N/A
J101 J305 J306 J402-J413 = CNBNC3P: Tolerance: N/A; User Part Number: UPN; alternate symbols: (); part number: CNBNC3P_SM-U.FL-R-SMT-1(01),E022198,CNHIROSE-U_FL-R-SMT-1; tolerance: N/A
J201 J202 J301 = CNBNC5P: Tolerance: N/A; User Part Number: UPN; alternate symbols: (CNAMPHENOL132255-11_ALT); part number: CNBNC5P_SM-132255-11,E017863,CNAMPHENOL132255-11; tolerance: N/A
J401 = CNBNC5P: Tolerance: N/A; User Part Number: UPN; alternate symbols: (); part number: CNBNC5P_TH-142-0701-201,E000916,CNJOHNSON142-0701-201; tolerance: N/A
L401 = IND: User Part Number: UPN; alternate symbols: (L0402L); part number: IND_SM-TBD0402,TBD0402,E002418,L0402
L612 = IND: User Part Number: UPN; alternate symbols: (); part number: IND_SM-TBD0201,TBD0201,E007524,L0201
L900 L901 = IND: User Part Number: UPN; Tolerance: 20; alternate symbols: (); part number: IND_SM-2.2UH,20,E016651,LSMSQ157H83; tolerance: 20
L902 L903 = IND: User Part Number: UPN; Tolerance: 20; alternate symbols: (); part number: IND_SM-6.8UH,20,E017909,LSMSQ157H122; tolerance: 20
P101 = CN20P: Tolerance: N/A; User Part Number: UPN; alternate symbols: (); part number: CN20P_TH-TSW-110-08-G-D,E000753,CNBERG2X10H330LD36; tolerance: N/A
P102 = CN16P_ODD_EVEN: Tolerance: N/A; User Part Number: UPN; alternate symbols: (); part number: CN16P_ODD_EVEN_TH-TSW-108-08-G-D,E007547,CNSAMTECTSW-108-08-G-D-ST; tolerance: N/A
P103 P104 = CN10P: User Part Number: UPN; Tolerance: N/A; alternate symbols: (); part number: CN10P_TH-TSW-105-08-G-D,E006587,CNSAMTEC2X5H338LD36; tolerance: N/A
P701 = CN20P_V2: Tolerance: N/A; User Part Number: UPN; alternate symbols: (); part number: CN20P_V2_SM-FTSH-110-01-L-DV-K,E020976,CNHDR2X10H251; tolerance: N/A
P801 = CN400P_A_K: User Part Number: UPN; Tolerance: N/A; alternate symbols: (); part number: CN400P_A_K_SM-ASP-134488-01,E011384,CNSAMTECASP-134488-01; tolerance: N/A
P901 = CN2P: User Part Number: UPN; Tolerance: N/A; alternate symbols: (); part number: CN2P_TH-Z5.530.3225.0,E008161,CNWIELAND3225; tolerance: N/A
P902 = CN3P: User Part Number: UPN; Tolerance: N/A; alternate symbols: (); part number: CN3P_TH-TSW-103-08-G-S,E000812,CNBERG1X3H205LD36; tolerance: N/A
P903-P907 = CN2P: User Part Number: UPN; Tolerance: N/A; alternate symbols: (); part number: CN2P_TH-TSW-102-08-G-S,E006296,CNSAMTEC1X2H330LD36; tolerance: N/A
Q901 = TRANNMOSFET_2PAD: Tolerance: N/A; User Part Number: UPN; alternate symbols: (); part number: TRANNMOSFET_2PAD_SM-SIA906EDJ-T1-GE3,E015819,POWERPAKSC70-6; tolerance: N/A
R101 = RES: Tolerance: 1; User Part Number: UPN; alternate symbols: (); part number: RES_SM-14.3K,E014068,1/20W,1,R0201; tolerance: 1
R102-R111 R113 R116-R120 R832 R833 = RES: Tolerance: 1; User Part Number: UPN; alternate symbols: (); part number: RES_SM-10K,E004011,1/20W,1,R0201; tolerance: 1
R112 = RES: Tolerance: 1; User Part Number: UPN; alternate symbols: (); part number: RES_SM-1K,E004010,1/20W,1,R0201; tolerance: 1
R121 R405 R406 R418 R423 R426-R428 R431 R434 R450 = RES: Tolerance: 1; User Part Number: UPN; alternate symbols: (); part number: RES_SM-100,E007239,1/20W,1,R0201; tolerance: 1
R202 R205 R206 R209 R212 R213 R302 R304 R305 R453 R454 R612 R702 R704-R707 R801 R804-R813 R816-R831 R834-R837 R839 R840 R842-R847 R912 = RES: Tolerance: 5; User Part Number: UPN; alternate symbols: (); part number: RES_SM-0,E004015,1/20W,5,R0201; tolerance: 5
R401 R412 = RES: User Part Number: UPN; Tolerance: 1; alternate symbols: (R0402L); part number: RES_SM-49.9,E003750,1/16W,1,R0402; tolerance: 1
R402 R407-R411 R413-R417 R419-R422 R424 R425 R429 R430 R432 R433 R435-R438 R444 R445 R448 R449 R451 R452 R601 R603-R610 R915 R921 R925 R929 R941 R942 = RES: User Part Number: UPN; Tolerance: 5; alternate symbols: (R0402L,R0402L_ALT); part number: RES_SM-0,E003438,N/A,5,R0402; tolerance: 5
R403 R404 = RES: User Part Number: UPN; Tolerance: 1; alternate symbols: (R0402L); part number: RES_SM-24.9,E003773,1/16W,1,R0402; tolerance: 1
R439 = RES: User Part Number: UPN; Tolerance: 1; alternate symbols: (R0402L); part number: RES_SM-10.2K,E019451,1/16W,1,R0402; tolerance: 1
R440-R443 R715-R727 R914 R920 R922 R924 R928 = RES: User Part Number: UPN; Tolerance: 1; alternate symbols: (R0402L,R0402L_ALT); part number: RES_SM-10K,E003751,1/10W,1,R0402; tolerance: 1
R446 R447 R935 = RES: User Part Number: UPN; Tolerance: 1; alternate symbols: (R0402L); part number: RES_SM-200,E003753,1/16W,1,R0402; tolerance: 1
R613 = RES: User Part Number: UPN; Tolerance: 1; alternate symbols: (R0402L); part number: RES_SM-0.1,E017078,1/6W,1,R0402; tolerance: 1
R701 = RES: Tolerance: 1; User Part Number: UPN; alternate symbols: (); part number: RES_SM-47K,E020665,1/20W,1,R0201; tolerance: 1
R708-R713 = RES: Tolerance: 1; User Part Number: UPN; alternate symbols: (); part number: RES_SM-20K,E004013,1/20W,1,R0201; tolerance: 1
R714 R909 = RES: User Part Number: UPN; Tolerance: 1; alternate symbols: (R0402L); part number: RES_SM-56K,E017978,1/10W,1,R0402; tolerance: 1
R848 = RES: User Part Number: UPN; Tolerance: 5; alternate symbols: (R0402L); part number: RES_SM-1K,E020936,1/16W,5,R0402; tolerance: 5
R901 = RES: Tolerance: 1; User Part Number: UPN; alternate symbols: (R0603L); part number: RES_SM-2K,E017866,1/16W,1,R0603; tolerance: 1
R902 = RES: Tolerance: 1; User Part Number: UPN; alternate symbols: (); part number: RES_SM-200,E004008,1/20W,1,R0201; tolerance: 1
R903 R906 = RES: User Part Number: UPN; Tolerance: 5; alternate symbols: (R0402L); part number: RES_SM-100K,E003464,1/10W,5,R0402; tolerance: 5
R904 R907 = RES: User Part Number: UPN; Tolerance: 1; alternate symbols: (R0402L); part number: RES_SM-10K,E003751,1/10W,1,R0402; tolerance: 1
R905 = RES: User Part Number: UPN; Tolerance: 1; alternate symbols: (R0402L); part number: RES_SM-43.2K,E018504,1/10W,1,R0402; tolerance: 1
R908 R911 R939 = RES: User Part Number: UPN; Tolerance: 1; alternate symbols: (R0402L); part number: RES_SM-20K,E003791,1/16W,1,R0402; tolerance: 1
R910 = RES: User Part Number: UPN; Tolerance: 1; alternate symbols: (R0402L); part number: RES_SM-14K,E019660,1/16W,1,R0402; tolerance: 1
R913 = RES: User Part Number: UPN; Tolerance: 1; alternate symbols: (R0402L); part number: RES_SM-22.1K,E007152,1/16W,1,R0402; tolerance: 1
R916 R923 = RES: User Part Number: UPN; Tolerance: 1; alternate symbols: (R0402L); part number: RES_SM-6.34K,E003777,1/16W,1,R0402; tolerance: 1
R917 = RES: User Part Number: UPN; Tolerance: 1; alternate symbols: (R0402L); part number: RES_SM-10.7K,E019637,1/16W,1,R0402; tolerance: 1
R918 R919 = RES: User Part Number: UPN; Tolerance: 1; alternate symbols: (R0402L,R0402L_ALT); part number: RES_SM-47K,E008189,1/16W,1,R0402; tolerance: 1
R926 = RES: User Part Number: UPN; Tolerance: 1; alternate symbols: (R0402L); part number: RES_SM-37.4K,E017173,1/10W,1,R0402; tolerance: 1
R927 = RES: User Part Number: UPN; Tolerance: 1; alternate symbols: (R0402L); part number: RES_SM-31.6K,E019881,1/10W,1,R0402; tolerance: 1
R930 = RES: User Part Number: UPN; Tolerance: 1; alternate symbols: (R0402L); part number: RES_SM-27.4K,E021819,1/10W,1,R0402; tolerance: 1
R931 = RES: User Part Number: UPN; Tolerance: 1; alternate symbols: (R0402L); part number: RES_SM-12.7K,E019976,1/10W,1,R0402; tolerance: 1
R932-R934 = RES: Tolerance: 1; User Part Number: UPN; alternate symbols: (R0603L); part number: RES_SM-0.1,E016658,1/10W,1,R0603; tolerance: 1
R936 R938 = RES: Tolerance: 5; User Part Number: UPN; alternate symbols: (R0603L); part number: RES_SM-0,E006826,1/10W,5,R0603; tolerance: 5
R937 = RES: Tolerance: 5; User Part Number: UPN; alternate symbols: (R0603L); part number: RES_SM-0.47,E015794,1/10W,5,R0603; tolerance: 5
R940 = RES: User Part Number: UPN; Tolerance: 1; alternate symbols: (R0402L); part number: RES_SM-4.99K,E006643,1/16W,1,R0402; tolerance: 1
T201 T202 = XFMRTCMXXXX_V5: Tolerance: N/A; User Part Number: UPN; alternate symbols: (); part number: XFMRTCMXXXX_V5_SM-TCM1-83X+,E018600,TSML150W160H160; tolerance: N/A
T301 = XFMRBD0826: User Part Number: UPN; Tolerance: N/A; alternate symbols: (); part number: XFMRBD0826_SM-HHM1595A1,E016462,T0805_A; tolerance: N/A
T401 = XFMRETC1: Tolerance: N/A; User Part Number: UPN; alternate symbols: (); part number: XFMRETC1_SM-MABA-007159-000000,E006308,ETC1; tolerance: N/A
TP400-TP403 TP601-TP613 TP701 TP702 TP803-TP806 TP809-TP819 TP901-TP904 = CNTP1P: Tolerance: N/A; User Part Number: UPN; alternate symbols: (); part number: CNTP1P_TH-WHT,E005683,CNKEY5001TP; tolerance: N/A
U101 = ADRV9008_1: User Part Number: UPN; Tolerance: N/A; alternate symbols: (); part number: ADRV9008_1_SM-ADRV9008BBCZ-1,E031769,BGA196; tolerance: N/A
U102 = ICS25FL208K: Tolerance: N/A; User Part Number: UPN; alternate symbols: (); part number: ICS25FL208K_SM-S25FL208K0RMFI041,E019626,SO8; tolerance: N/A
U401 = AD9528: User Part Number: UPN; Tolerance: N/A; alternate symbols: (); part number: AD9528_SM-AD9528BCPZ,E019427,QFN72_10X10_PAD5_3X5_3; tolerance: N/A
U402 = CMOSNC7WV125K8X: Tolerance: N/A; User Part Number: UPN; alternate symbols: (); part number: CMOSNC7WV125K8X_SM-NC7WV125K8X,E017378,US8; tolerance: N/A
U403 = ADG3304: Tolerance: N/A; User Part Number: UPN; alternate symbols: (); part number: ADG3304_SM-ADG3304SRU-EP,E020776,TSSOP14; tolerance: N/A
U404 = ADG3301: Tolerance: N/A; User Part Number: UPN; alternate symbols: (); part number: ADG3301_SM-ADG3301BKSZ,E010847,SC70-6; tolerance: N/A
U405 = NC7WZ17P6X: Tolerance: N/A; User Part Number: UPN; alternate symbols: (); part number: NC7WZ17P6X_SM-NC7WZ16P6X,E002060,SC70; tolerance: N/A
U702 = ICM24CXX: Tolerance: N/A; User Part Number: UPN; alternate symbols: (); part number: ICM24CXX_SM-M24C02-FDW6TP,E031427,TSSOP8; tolerance: N/A
U703 = AD7291: User Part Number: UPN; Tolerance: N/A; alternate symbols: (); part number: AD7291_SM-AD7291BCPZ,E017361,QFN20_4X4_PAD2_6X2_6; tolerance: N/A
U901 = ADP5054: User Part Number: UPN; Tolerance: N/A; alternate symbols: (); part number: ADP5054_SM-ADP5054ACPZ,E019222,QFN48_7X7_PAD5_6X5_6; tolerance: N/A
U902 = ADP125: Tolerance: N/A; User Part Number: UPN; alternate symbols: (); part number: ADP125_SM-ADP125ARHZ-R7,E012587,MSOP8_PAD2_16X1_73; tolerance: N/A
Y401 = XTALOSC6P: Tolerance: N/A; User Part Number: UPN; alternate symbols: (); part number: XTALOSC6P_SM-122.88MEGHZ,E013348,YSML276W197H71; tolerance: N/A
Y402 = XTALOSC6P_V2: Tolerance: N/A; User Part Number: UPN; alternate symbols: (); part number: XTALOSC6P_V2_SM-122.88MEGHZ,E010834,YSML555W358H240; tolerance: N/A

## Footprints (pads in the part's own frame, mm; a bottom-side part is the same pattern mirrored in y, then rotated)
BGA196
  round 0.356 smd: A1(-5.2,-5.2) A2(-5.2,-4.4) A3(-5.2,-3.6) A4(-5.2,-2.8) A5(-5.2,-2) A6(-5.2,-1.2) A7(-5.2,-0.4) A8(-5.2,0.4) A9(-5.2,1.2) A10(-5.2,2) A11(-5.2,2.8) A12(-5.2,3.6) A13(-5.2,4.4) A14(-5.2,5.2) B1(-4.4,-5.2) B2(-4.4,-4.4) B3(-4.4,-3.6) B4(-4.4,-2.8) B5(-4.4,-2) B6(-4.4,-1.2) B7(-4.4,-0.4) B8(-4.4,0.4) B9(-4.4,1.2) B10(-4.4,2) B11(-4.4,2.8) B12(-4.4,3.6) B13(-4.4,4.4) B14(-4.4,5.2) C1(-3.6,-5.2) C2(-3.6,-4.4) C3(-3.6,-3.6) C4(-3.6,-2.8) C5(-3.6,-2) C6(-3.6,-1.2) C7(-3.6,-0.4) C8(-3.6,0.4) C9(-3.6,1.2) C10(-3.6,2) C11(-3.6,2.8) C12(-3.6,3.6) C13(-3.6,4.4) C14(-3.6,5.2) D1(-2.8,-5.2) D2(-2.8,-4.4) D3(-2.8,-3.6) D4(-2.8,-2.8) D5(-2.8,-2) D6(-2.8,-1.2) D7(-2.8,-0.4) D8(-2.8,0.4) D9(-2.8,1.2) D10(-2.8,2) D11(-2.8,2.8) D12(-2.8,3.6) D13(-2.8,4.4) D14(-2.8,5.2) E1(-2,-5.2) E2(-2,-4.4) E3(-2,-3.6) E4(-2,-2.8) E5(-2,-2) E6(-2,-1.2) E7(-2,-0.4) E8(-2,0.4) E9(-2,1.2) E10(-2,2) E11(-2,2.8) E12(-2,3.6) E13(-2,4.4) E14(-2,5.2) F1(-1.2,-5.2) F2(-1.2,-4.4) F3(-1.2,-3.6) F4(-1.2,-2.8) F5(-1.2,-2) F6(-1.2,-1.2) F7(-1.2,-0.4) F8(-1.2,0.4) F9(-1.2,1.2) F10(-1.2,2) F11(-1.2,2.8) F12(-1.2,3.6) F13(-1.2,4.4) F14(-1.2,5.2) G1(-0.4,-5.2) G2(-0.4,-4.4) G3(-0.4,-3.6) G4(-0.4,-2.8) G5(-0.4,-2) G6(-0.4,-1.2) G7(-0.4,-0.4) G8(-0.4,0.4) G9(-0.4,1.2) G10(-0.4,2) G11(-0.4,2.8) G12(-0.4,3.6) G13(-0.4,4.4) G14(-0.4,5.2) H1(0.4,-5.2) H2(0.4,-4.4) H3(0.4,-3.6) H4(0.4,-2.8) H5(0.4,-2) H6(0.4,-1.2) H7(0.4,-0.4) H8(0.4,0.4) H9(0.4,1.2) H10(0.4,2) H11(0.4,2.8) H12(0.4,3.6) H13(0.4,4.4) H14(0.4,5.2) J1(1.2,-5.2) J2(1.2,-4.4) J3(1.2,-3.6) J4(1.2,-2.8) J5(1.2,-2) J6(1.2,-1.2) J7(1.2,-0.4) J8(1.2,0.4) J9(1.2,1.2) J10(1.2,2) J11(1.2,2.8) J12(1.2,3.6) J13(1.2,4.4) J14(1.2,5.2) K1(2,-5.2) K2(2,-4.4) K3(2,-3.6) K4(2,-2.8) K5(2,-2) K6(2,-1.2) K7(2,-0.4) K8(2,0.4) K9(2,1.2) K10(2,2) K11(2,2.8) K12(2,3.6) K13(2,4.4) K14(2,5.2) L1(2.8,-5.2) L2(2.8,-4.4) L3(2.8,-3.6) L4(2.8,-2.8) L5(2.8,-2) L6(2.8,-1.2) L7(2.8,-0.4) L8(2.8,0.4) L9(2.8,1.2) L10(2.8,2) L11(2.8,2.8) L12(2.8,3.6) L13(2.8,4.4) L14(2.8,5.2) M1(3.6,-5.2) M2(3.6,-4.4) M3(3.6,-3.6) M4(3.6,-2.8) M5(3.6,-2) M6(3.6,-1.2) M7(3.6,-0.4) M8(3.6,0.4) M9(3.6,1.2) M10(3.6,2) M11(3.6,2.8) M12(3.6,3.6) M13(3.6,4.4) M14(3.6,5.2) N1(4.4,-5.2) N2(4.4,-4.4) N3(4.4,-3.6) N4(4.4,-2.8) N5(4.4,-2) N6(4.4,-1.2) N7(4.4,-0.4) N8(4.4,0.4) N9(4.4,1.2) N10(4.4,2) N11(4.4,2.8) N12(4.4,3.6) N13(4.4,4.4) N14(4.4,5.2) P1(5.2,-5.2) P2(5.2,-4.4) P3(5.2,-3.6) P4(5.2,-2.8) P5(5.2,-2) P6(5.2,-1.2) P7(5.2,-0.4) P8(5.2,0.4) P9(5.2,1.2) P10(5.2,2) P11(5.2,2.8) P12(5.2,3.6) P13(5.2,4.4) P14(5.2,5.2)
C0201
  rect 0.305x0.406 smd: 1(-0.317,0) 2(0.317,0)
C0402
  rect 0.61x0.61 smd: 1(-0.495,0) 2(0.495,0)
C0402#2
  rect 0.483x0.559 smd: 1(-0.438,0) 2(0.438,0)
C0603
  rect 1.092x1.194 smd: 1(-0.851,0) 2(0.851,0)
C0603#2
  rect 0.762x0.889 smd: 1(-0.7,0) 2(0.7,0)
C0805H53
  rect 1.295x1.6 smd: 1(-0.953,0) 2(0.953,0)
C0805H60
  rect 1.295x1.6 smd: 1(-0.953,0) 2(0.953,0)
C1210
  rect 1.575x2.692 smd: 1(-1.397,0) 2(1.397,0)
C1210-2
  rect 1.575x2.692 smd: 1(-1.397,0) 2(1.397,0)
C1210-2#2
  rect 1.092x2.057 smd: 1(-1.646,0) 2(1.646,0)
CNAMPHENOL132255-11
  rect 2.54x0.432 smd: 1(-0.508,0)
  rect 6.35x1.524 hole 0.508: 2(-2.413,4.25) 4(-2.413,-4.25)
  round 0.305 smd: 3(-2.413,4.25) 5(-2.413,-4.25)
CNBERG1X3H205LD36
  rect 1.651x1.651 hole 1.143: 1(0,0)
  round 1.651 hole 1.143: 2(2.54,0) 3(5.08,0)
CNBERG2X10H330LD36
  rect 1.651x1.651 hole 1.143: 1(0,0)
  round 1.651 hole 1.143: 2(0,2.54) 3(2.54,0) 4(2.54,2.54) 5(5.08,0) 6(5.08,2.54) 7(7.62,0) 8(7.62,2.54) 9(10.16,0) 10(10.16,2.54) 11(12.7,0) 12(12.7,2.54) 13(15.24,0) 14(15.24,2.54) 15(17.78,0) 16(17.78,2.54) 17(20.32,0) 18(20.32,2.54) 19(22.86,0) 20(22.86,2.54)
CNHDR2X10H251
  rect 0.737x2.794 smd: 1(-5.715,-2.032) 2(-5.715,2.032) 3(-4.445,-2.032) 4(-4.445,2.032) 5(-3.175,-2.032) 6(-3.175,2.032) 7(-1.905,-2.032) 8(-1.905,2.032) 9(-0.635,-2.032) 10(-0.635,2.032) 11(0.635,-2.032) 12(0.635,2.032) 13(1.905,-2.032) 14(1.905,2.032) 15(3.175,-2.032) 16(3.175,2.032) 17(4.445,-2.032) 18(4.445,2.032) 19(5.715,-2.032) 20(5.715,2.032)
CNHIROSE-U_FL-R-SMT-1
  rect 0.991x1.041 smd: 1(0,-1.521)
  rect 1.041x2.21 smd: 2(-1.471,0) 3(1.471,0)
CNJOHNSON142-0701-201
  round 2.032 hole 1.524: 1(0,0) 2(-2.54,2.54) 3(2.54,2.54) 4(2.54,-2.54) 5(-2.54,-2.54)
CNKEY5001TP
  round 1.524 hole 1.016: 1(0,0)
CNSAMTEC1X2H330LD36
  rect 1.651x1.651 hole 1.143: 1(-1.27,0)
  round 1.651 hole 1.143: 2(1.27,0)
CNSAMTEC2X5H338LD36
  rect 1.651x1.651 hole 1.143: 1(0,0)
  round 1.651 hole 1.143: 2(0,2.54) 3(2.54,0) 4(2.54,2.54) 5(5.08,0) 6(5.08,2.54) 7(7.62,0) 8(7.62,2.54) 9(10.16,0) 10(10.16,2.54)
CNSAMTECASP-134488-01
  round 2.54 hole 1.27 unplated: (-2.426,5.715) (51.956,8.763)
  round 0.889 smd: A1(0,0) A2(1.27,0) A3(2.54,0) A4(3.81,0) A5(5.08,0) A6(6.35,0) A7(7.62,0) A8(8.89,0) A9(10.16,0) A10(11.43,0) A11(12.7,0) A12(13.97,0) A13(15.24,0) A14(16.51,0) A15(17.78,0) A16(19.05,0) A17(20.32,0) A18(21.59,0) A19(22.86,0) A20(24.13,0) A21(25.4,0) A22(26.67,0) A23(27.94,0) A24(29.21,0) A25(30.48,0) A26(31.75,0) A27(33.02,0) A28(34.29,0) A29(35.56,0) A30(36.83,0) A31(38.1,0) A32(39.37,0) A33(40.64,0) A34(41.91,0) A35(43.18,0) A36(44.45,0) A37(45.72,0) A38(46.99,0) A39(48.26,0) A40(49.53,0) B1(0,1.27) B2(1.27,1.27) B3(2.54,1.27) B4(3.81,1.27) B5(5.08,1.27) B6(6.35,1.27) B7(7.62,1.27) B8(8.89,1.27) B9(10.16,1.27) B10(11.43,1.27) B11(12.7,1.27) B12(13.97,1.27) B13(15.24,1.27) B14(16.51,1.27) B15(17.78,1.27) B16(19.05,1.27) B17(20.32,1.27) B18(21.59,1.27) B19(22.86,1.27) B20(24.13,1.27) B21(25.4,1.27) B22(26.67,1.27) B23(27.94,1.27) B24(29.21,1.27) B25(30.48,1.27) B26(31.75,1.27) B27(33.02,1.27) B28(34.29,1.27) B29(35.56,1.27) B30(36.83,1.27) B31(38.1,1.27) B32(39.37,1.27) B33(40.64,1.27) B34(41.91,1.27) B35(43.18,1.27) B36(44.45,1.27) B37(45.72,1.27) B38(46.99,1.27) B39(48.26,1.27) B40(49.53,1.27) C1(0,2.54) C2(1.27,2.54) C3(2.54,2.54) C4(3.81,2.54) C5(5.08,2.54) C6(6.35,2.54) C7(7.62,2.54) C8(8.89,2.54) C9(10.16,2.54) C10(11.43,2.54) C11(12.7,2.54) C12(13.97,2.54) C13(15.24,2.54) C14(16.51,2.54) C15(17.78,2.54) C16(19.05,2.54) C17(20.32,2.54) C18(21.59,2.54) C19(22.86,2.54) C20(24.13,2.54) C21(25.4,2.54) C22(26.67,2.54) C23(27.94,2.54) C24(29.21,2.54) C25(30.48,2.54) C26(31.75,2.54) C27(33.02,2.54) C28(34.29,2.54) C29(35.56,2.54) C30(36.83,2.54) C31(38.1,2.54) C32(39.37,2.54) C33(40.64,2.54) C34(41.91,2.54) C35(43.18,2.54) C36(44.45,2.54) C37(45.72,2.54) C38(46.99,2.54) C39(48.26,2.54) C40(49.53,2.54) D1(0,3.81) D2(1.27,3.81) D3(2.54,3.81) D4(3.81,3.81) D5(5.08,3.81) D6(6.35,3.81) D7(7.62,3.81) D8(8.89,3.81) D9(10.16,3.81) D10(11.43,3.81) D11(12.7,3.81) D12(13.97,3.81) D13(15.24,3.81) D14(16.51,3.81) D15(17.78,3.81) D16(19.05,3.81) D17(20.32,3.81) D18(21.59,3.81) D19(22.86,3.81) D20(24.13,3.81) D21(25.4,3.81) D22(26.67,3.81) D23(27.94,3.81) D24(29.21,3.81) D25(30.48,3.81) D26(31.75,3.81) D27(33.02,3.81) D28(34.29,3.81) D29(35.56,3.81) D30(36.83,3.81) D31(38.1,3.81) D32(39.37,3.81) D33(40.64,3.81) D34(41.91,3.81) D35(43.18,3.81) D36(44.45,3.81) D37(45.72,3.81) D38(46.99,3.81) D39(48.26,3.81) D40(49.53,3.81) E1(0,5.08) E2(1.27,5.08) E3(2.54,5.08) E4(3.81,5.08) E5(5.08,5.08) E6(6.35,5.08) E7(7.62,5.08) E8(8.89,5.08) E9(10.16,5.08) E10(11.43,5.08) E11(12.7,5.08) E12(13.97,5.08) E13(15.24,5.08) E14(16.51,5.08) E15(17.78,5.08) E16(19.05,5.08) E17(20.32,5.08) E18(21.59,5.08) E19(22.86,5.08) E20(24.13,5.08) E21(25.4,5.08) E22(26.67,5.08) E23(27.94,5.08) E24(29.21,5.08) E25(30.48,5.08) E26(31.75,5.08) E27(33.02,5.08) E28(34.29,5.08) E29(35.56,5.08) E30(36.83,5.08) E31(38.1,5.08) E32(39.37,5.08) E33(40.64,5.08) E34(41.91,5.08) E35(43.18,5.08) E36(44.45,5.08) E37(45.72,5.08) E38(46.99,5.08) E39(48.26,5.08) E40(49.53,5.08) F1(0,6.35) F2(1.27,6.35) F3(2.54,6.35) F4(3.81,6.35) F5(5.08,6.35) F6(6.35,6.35) F7(7.62,6.35) F8(8.89,6.35) F9(10.16,6.35) F10(11.43,6.35) F11(12.7,6.35) F12(13.97,6.35) F13(15.24,6.35) F14(16.51,6.35) F15(17.78,6.35) F16(19.05,6.35) F17(20.32,6.35) F18(21.59,6.35) F19(22.86,6.35) F20(24.13,6.35) F21(25.4,6.35) F22(26.67,6.35) F23(27.94,6.35) F24(29.21,6.35) F25(30.48,6.35) F26(31.75,6.35) F27(33.02,6.35) F28(34.29,6.35) F29(35.56,6.35) F30(36.83,6.35) F31(38.1,6.35) F32(39.37,6.35) F33(40.64,6.35) F34(41.91,6.35) F35(43.18,6.35) F36(44.45,6.35) F37(45.72,6.35) F38(46.99,6.35) F39(48.26,6.35) F40(49.53,6.35) G1(0,7.62) G2(1.27,7.62) G3(2.54,7.62) G4(3.81,7.62) G5(5.08,7.62) G6(6.35,7.62) G7(7.62,7.62) G8(8.89,7.62) G9(10.16,7.62) G10(11.43,7.62) G11(12.7,7.62) G12(13.97,7.62) G13(15.24,7.62) G14(16.51,7.62) G15(17.78,7.62) G16(19.05,7.62) G17(20.32,7.62) G18(21.59,7.62) G19(22.86,7.62) G20(24.13,7.62) G21(25.4,7.62) G22(26.67,7.62) G23(27.94,7.62) G24(29.21,7.62) G25(30.48,7.62) G26(31.75,7.62) G27(33.02,7.62) G28(34.29,7.62) G29(35.56,7.62) G30(36.83,7.62) G31(38.1,7.62) G32(39.37,7.62) G33(40.64,7.62) G34(41.91,7.62) G35(43.18,7.62) G36(44.45,7.62) G37(45.72,7.62) G38(46.99,7.62) G39(48.26,7.62) G40(49.53,7.62) H1(0,8.89) H2(1.27,8.89) H3(2.54,8.89) H4(3.81,8.89) H5(5.08,8.89) H6(6.35,8.89) H7(7.62,8.89) H8(8.89,8.89) H9(10.16,8.89) H10(11.43,8.89) H11(12.7,8.89) H12(13.97,8.89) H13(15.24,8.89) H14(16.51,8.89) H15(17.78,8.89) H16(19.05,8.89) H17(20.32,8.89) H18(21.59,8.89) H19(22.86,8.89) H20(24.13,8.89) H21(25.4,8.89) H22(26.67,8.89) H23(27.94,8.89) H24(29.21,8.89) H25(30.48,8.89) H26(31.75,8.89) H27(33.02,8.89) H28(34.29,8.89) H29(35.56,8.89) H30(36.83,8.89) H31(38.1,8.89) H32(39.37,8.89) H33(40.64,8.89) H34(41.91,8.89) H35(43.18,8.89) H36(44.45,8.89) H37(45.72,8.89) H38(46.99,8.89) H39(48.26,8.89) H40(49.53,8.89) J1(0,10.16) J2(1.27,10.16) J3(2.54,10.16) J4(3.81,10.16) J5(5.08,10.16) J6(6.35,10.16) J7(7.62,10.16) J8(8.89,10.16) J9(10.16,10.16) J10(11.43,10.16) J11(12.7,10.16) J12(13.97,10.16) J13(15.24,10.16) J14(16.51,10.16) J15(17.78,10.16) J16(19.05,10.16) J17(20.32,10.16) J18(21.59,10.16) J19(22.86,10.16) J20(24.13,10.16) J21(25.4,10.16) J22(26.67,10.16) J23(27.94,10.16) J24(29.21,10.16) J25(30.48,10.16) J26(31.75,10.16) J27(33.02,10.16) J28(34.29,10.16) J29(35.56,10.16) J30(36.83,10.16) J31(38.1,10.16) J32(39.37,10.16) J33(40.64,10.16) J34(41.91,10.16) J35(43.18,10.16) J36(44.45,10.16) J37(45.72,10.16) J38(46.99,10.16) J39(48.26,10.16) J40(49.53,10.16) K1(0,11.43) K2(1.27,11.43) K3(2.54,11.43) K4(3.81,11.43) K5(5.08,11.43) K6(6.35,11.43) K7(7.62,11.43) K8(8.89,11.43) K9(10.16,11.43) K10(11.43,11.43) K11(12.7,11.43) K12(13.97,11.43) K13(15.24,11.43) K14(16.51,11.43) K15(17.78,11.43) K16(19.05,11.43) K17(20.32,11.43) K18(21.59,11.43) K19(22.86,11.43) K20(24.13,11.43) K21(25.4,11.43) K22(26.67,11.43) K23(27.94,11.43) K24(29.21,11.43) K25(30.48,11.43) K26(31.75,11.43) K27(33.02,11.43) K28(34.29,11.43) K29(35.56,11.43) K30(36.83,11.43) K31(38.1,11.43) K32(39.37,11.43) K33(40.64,11.43) K34(41.91,11.43) K35(43.18,11.43) K36(44.45,11.43) K37(45.72,11.43) K38(46.99,11.43) K39(48.26,11.43) K40(49.53,11.43)
